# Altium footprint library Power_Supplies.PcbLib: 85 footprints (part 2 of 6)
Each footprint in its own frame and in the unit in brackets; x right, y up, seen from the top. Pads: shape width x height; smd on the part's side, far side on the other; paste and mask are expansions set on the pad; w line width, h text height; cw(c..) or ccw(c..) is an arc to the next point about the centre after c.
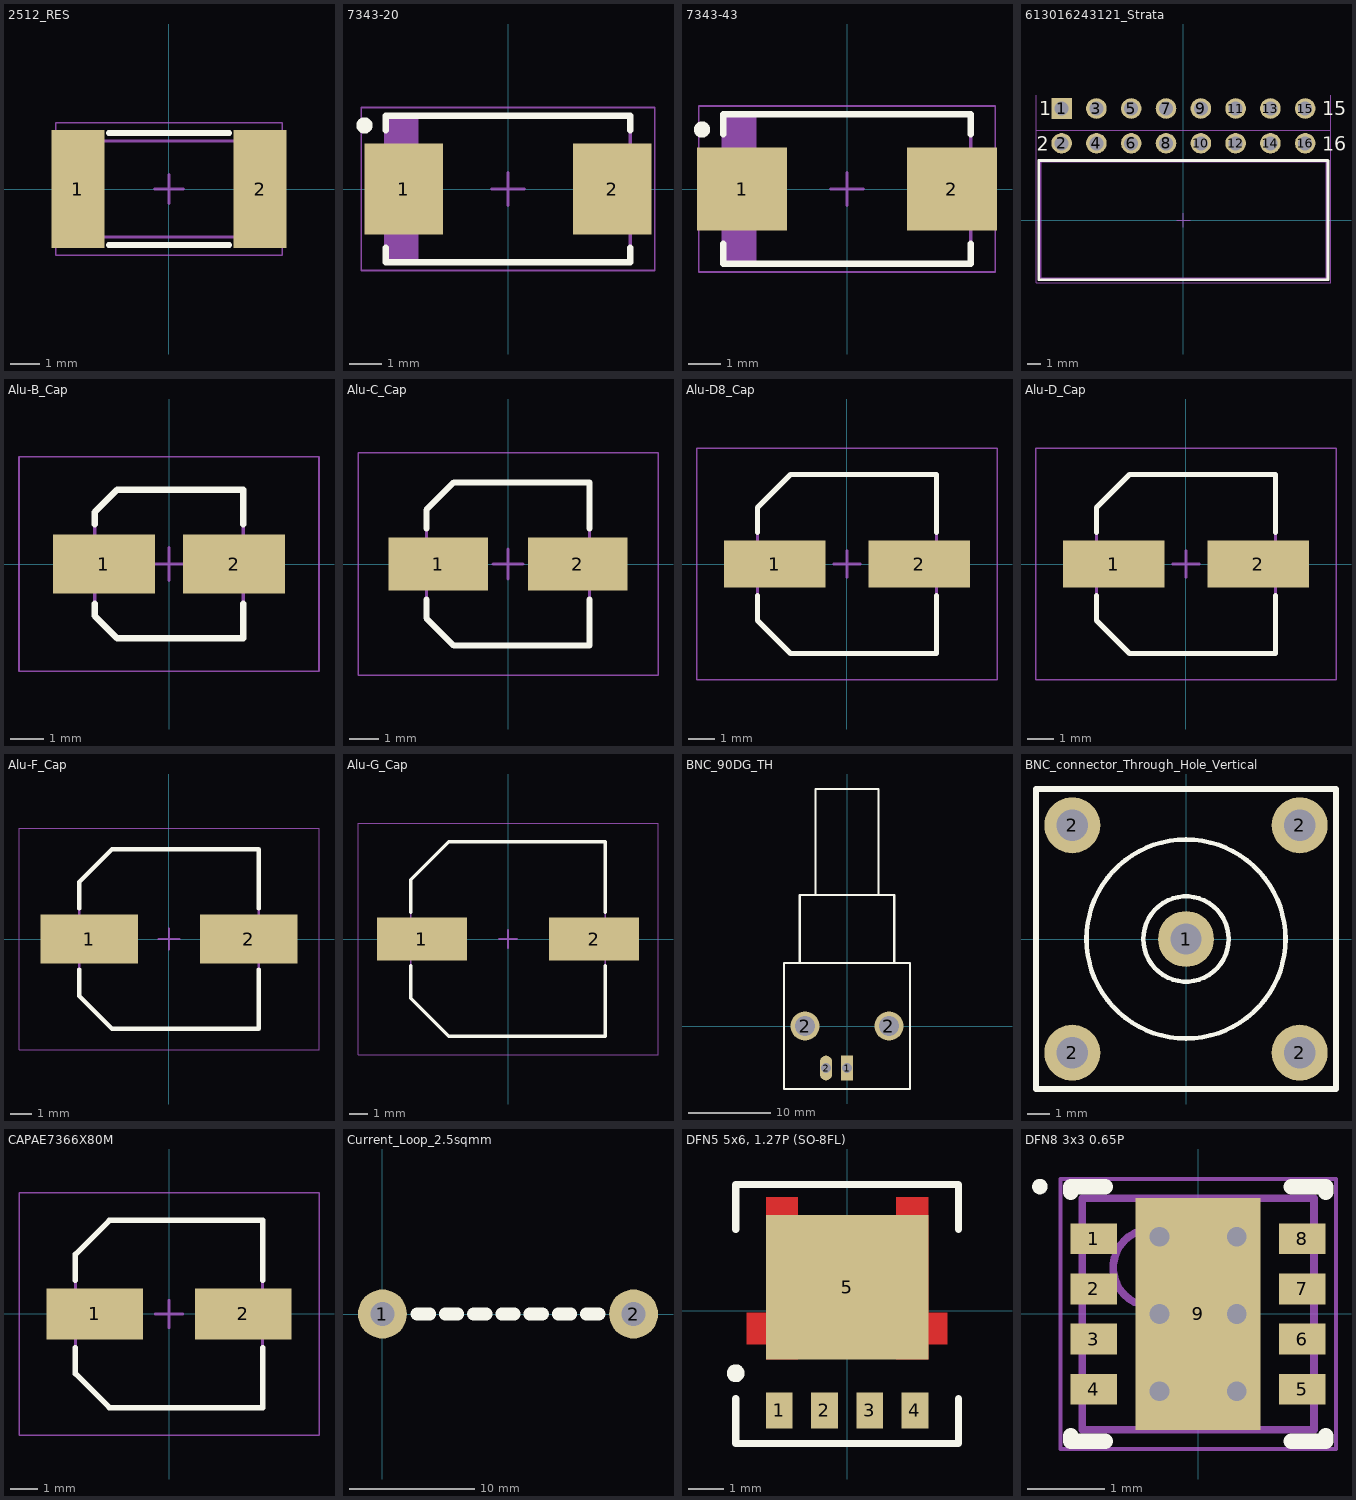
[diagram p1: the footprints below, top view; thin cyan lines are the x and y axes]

## 2512_RES [mm] "2512, Reflow, YAGEO"
height 0.65
pads (2):
  rect 1.8x4 smd: 1(-3.1,0) 2(3.1,0)
Top Overlay:
  lines w0.2: -2.05,-1.9 2.05,-1.9 ; -2.05,1.9 2.05,1.9
Mechanical 13:
  lines w0.1: -3.225,-1.625 -3.225,1.625 3.225,1.625 3.225,-1.625 -3.225,-1.625
Mechanical 15:
  lines w0.05: -3.85,-2.25 -3.85,2.25 3.85,2.25 3.85,-2.25 -3.85,-2.25
  lines w0.1: -0.5,0 0.5,0 ; 0,-0.5 0,0.5
3D body "2512_RES.step": height 0.65, standoff 0, extent -3.225,-1.625 3.225,1.625

## 7343-20 [mm] "7343-20, Polymer Aluminum Electrolytic Capacitors, GX Series, ody 7.3x4.3x1.9 mm"
height 2
pads (2):
  rect 2.4x2.8 smd: 1(-3.2,0) 2(3.2,0)
Top Overlay:
  circle w0.25: c-4.4,1.95 r0.125
  lines w0.2: -3.75,-1.8 -3.75,-2.25 3.75,-2.25 3.75,-1.8 ; -3.75,1.8 -3.75,2.25 3.75,2.25 3.75,1.8
Mechanical 13:
  rectangle: -3.75,-2.25 -2.741,2.25
  lines w0.1: -3.75,-2.25 3.75,-2.25 3.75,2.25 -3.75,2.25 -3.75,-2.25
Mechanical 15:
  lines w0.05: -4.5,-2.5 4.5,-2.5 4.5,2.5 -4.5,2.5 -4.5,-2.5
  lines w0.1: -0.5,0 0.5,0 ; 0,-0.5 0,0.5
3D body "7343-20.step": height 2, standoff 0, extent -3.97,-2.25 3.97,2.25

## 7343-43 [mm] "7343-43, Molded Capacitor, 2-Leads, Body 7.30x4.30mm, IPC Medium Density"
height 4.3
pads (2):
  rect 2.77x2.55 smd: 1(-3.22,0) 2(3.22,0)
Top Overlay:
  circle w0.25: c-4.45,1.825 r0.125
  lines w0.2: -3.8,-1.675 -3.8,-2.3 3.8,-2.3 3.8,-1.675 ; -3.8,1.675 -3.8,2.3 3.8,2.3 3.8,1.675
Mechanical 13:
  rectangle: -3.8,-2.3 -2.778,2.3
  lines w0.1: -3.8,-2.3 -3.8,2.3 3.8,2.3 3.8,-2.3 -3.8,-2.3
Mechanical 15:
  lines w0.05: -4.55,-2.55 -4.55,2.55 4.55,2.55 4.55,-2.55 -4.55,-2.55
  lines w0.1: -0.5,0 0.5,0 ; 0,-0.5 0,0.5
3D body "7343-43.step": height 4.3, standoff 0, extent -4.02,-2.3 4.02,2.3

## 613016243121_Strata [mm] "Socket Header, Pitch 2.54 mm, THT, Angled, dual row, 16p"
height 5.08
pads (16):
  rect 1.5x1.5 hole 1.02: 1(-8.89,8.15)
  round 1.5 hole 1.02: 2(-8.89,5.61) 3(-6.35,8.15) 4(-6.35,5.61) 5(-3.81,8.15) 6(-3.81,5.61) 7(-1.27,8.15) 8(-1.27,5.61) 9(1.27,8.15) 10(1.27,5.61) 11(3.81,8.15) 12(3.81,5.61) 13(6.35,8.15) 14(6.35,5.61) 15(8.89,8.15) 16(8.89,5.61)
Top Overlay:
  lines w0.2: -10.56,-4.35 10.56,-4.35 10.56,4.35 -10.56,4.35 -10.56,-4.35
  text "15" at 10.12,7.64 h1.02
  text "16" at 10.12,5.06 h1.02
  text "1" at -10.52,7.64 h1.02
  text "2" at -10.72,5.06 h1.02
Mechanical 13:
  lines w0.1: -10.41,-4.25 10.41,-4.25 10.41,4.25 -10.41,4.25 -10.41,-4.25
Mechanical 15:
  lines w0.05: -10.76,6.56 10.76,6.56 ; -10.76,9.1 -10.76,-4.55 10.76,-4.55 10.76,9.1 ; -0.5,0 0.5,0 ; 0,-0.5 0,0.5
3D body "613016243121.stp": height 5.05, standoff -3.25, extent -10.41,-4.25 10.41,8.35

## Alu-B_Cap [mm] "Aluminum Electrolytic Capacitor, Body 4.30x4.30x6.10mm, IPC Low Density"
height 6.1
pads (2):
  rect 3.1x1.8 smd: 1(-1.975,0) 2(1.975,0)
Top Overlay:
  lines w0.2: -2.25,-1.2 -2.25,-1.575 -1.575,-2.25 2.25,-2.25 2.25,-1.2 ; -2.25,1.2 -2.25,1.575 -1.575,2.25 2.25,2.25 2.25,1.2
Mechanical 13:
  lines w0.1: -2.25,-1.575 -2.25,1.575 -1.575,2.25 2.25,2.25 2.25,-2.25 -1.575,-2.25 -2.25,-1.575
Mechanical 15:
  lines w0.05: -4.55,-3.25 4.55,-3.25 4.55,3.25 -4.55,3.25 -4.55,-3.25
  lines w0.1: -0.5,0 0.5,0 ; 0,-0.5 0,0.5
3D body "D40H54_Alu-B_CapSMD.STEP": height 5.4, standoff 0, extent -2.3,-2.15 2.3,2.15

## Alu-C_Cap [mm] "Aluminum Electrolytic Capacitor, Body 5.30x5.30x6.10mm, IPC Low Density"
height 6.1
pads (2):
  rect 3.35x1.8 smd: 1(-2.35,0) 2(2.35,0)
Top Overlay:
  lines w0.2: -2.75,-1.2 -2.75,-1.825 -1.825,-2.75 2.75,-2.75 2.75,-1.2 ; -2.75,1.2 -2.75,1.825 -1.825,2.75 2.75,2.75 2.75,1.2
Mechanical 13:
  lines w0.1: -2.75,-1.825 -1.825,-2.75 2.75,-2.75 2.75,2.75 -1.825,2.75 -2.75,1.825 -2.75,-1.825
Mechanical 15:
  lines w0.05: -5.05,-3.75 -5.05,3.75 5.05,3.75 5.05,-3.75 -5.05,-3.75
  lines w0.1: -0.5,0 0.5,0 ; 0,-0.5 0,0.5
3D body "D50H54_Alu-C_CapSMD.STEP": height 5.41, standoff 0, extent -2.95,-2.65 2.95,2.65

## Alu-D8_Cap [mm] "Aluminum Electrolytic Capacitor, Body 6.60x6.60x8.00mm, IPC Low Density"
height 8
pads (2):
  rect 3.85x1.8 smd: 1(-2.75,0) 2(2.75,0)
Top Overlay:
  lines w0.2: -3.4,-1.2 -3.4,-2.15 -2.15,-3.4 3.4,-3.4 3.4,-1.2 ; -3.4,1.2 -3.4,2.15 -2.15,3.4 3.4,3.4 3.4,1.2
Mechanical 13:
  lines w0.1: -3.4,-2.15 -3.4,2.15 -2.15,3.4 3.4,3.4 3.4,-3.4 -2.15,-3.4 -3.4,-2.15
Mechanical 15:
  lines w0.05: -5.7,-4.4 5.7,-4.4 5.7,4.4 -5.7,4.4 -5.7,-4.4
  lines w0.1: -0.5,0 0.5,0 ; 0,-0.5 0,0.5
3D body "D63H77_Alu-D8_CapSMD.STEP": height 7.7, standoff 0, extent -3.5,-3.3 3.5,3.3

## Alu-D_Cap [mm] "Aluminum Electrolytic Capacitor, Body 6.60x6.60x8.00mm, IPC Low Density"
height 8
pads (2):
  rect 3.85x1.8 smd: 1(-2.75,0) 2(2.75,0)
Top Overlay:
  lines w0.2: -3.4,-1.2 -3.4,-2.15 -2.15,-3.4 3.4,-3.4 3.4,-1.2 ; -3.4,1.2 -3.4,2.15 -2.15,3.4 3.4,3.4 3.4,1.2
Mechanical 13:
  lines w0.1: -3.4,-2.15 -2.15,-3.4 3.4,-3.4 3.4,3.4 -2.15,3.4 -3.4,2.15 -3.4,-2.15
Mechanical 15:
  lines w0.05: -5.7,-4.4 -5.7,4.4 5.7,4.4 5.7,-4.4 -5.7,-4.4
  lines w0.1: -0.5,0 0.5,0 ; 0,-0.5 0,0.5
3D body "D63H54_Alu-D_CapSMD.STEP": height 5.4, standoff 0, extent -3.5,-3.3 3.5,3.3

## Alu-F_Cap [mm] "Aluminum Electrolytic Capacitor, Body 8.30x8.30x10.50mm, IPC Low Density"
height 10.5
pads (2):
  rect 4.6x2.3 smd: 1(-3.775,0) 2(3.775,0)
Top Overlay:
  lines w0.2: -4.25,-1.45 -4.25,-2.7 -2.7,-4.25 4.25,-4.25 4.25,-1.45 ; -4.25,1.45 -4.25,2.7 -2.7,4.25 4.25,4.25 4.25,1.45
Mechanical 13:
  lines w0.1: -4.25,-2.7 -4.25,2.7 -2.7,4.25 4.25,4.25 4.25,-4.25 -2.7,-4.25 -4.25,-2.7
Mechanical 15:
  lines w0.05: -7.1,-5.25 7.1,-5.25 7.1,5.25 -7.1,5.25 -7.1,-5.25
  lines w0.1: -0.5,0 0.5,0 ; 0,-0.5 0,0.5
3D body "D80H102_Alu-F_CapSMD.STEP": height 10.2, standoff 0, extent -4.95,-4.15 4.95,4.15

## Alu-G_Cap [mm] "Aluminum Electrolytic Capacitor, Body 10.30x10.30x10.50mm, IPC Low Density"
height 10.5
pads (2):
  rect 4.85x2.3 smd: 1(-4.65,0) 2(4.65,0)
Top Overlay:
  lines w0.2: -5.25,-1.45 -5.25,-3.2 -3.2,-5.25 5.25,-5.25 5.25,-1.45 ; -5.25,1.45 -5.25,3.2 -3.2,5.25 5.25,5.25 5.25,1.45
Mechanical 13:
  lines w0.1: -5.25,-3.2 -3.2,-5.25 5.25,-5.25 5.25,5.25 -3.2,5.25 -5.25,3.2 -5.25,-3.2
Mechanical 15:
  lines w0.05: -8.1,-6.25 -8.1,6.25 8.1,6.25 8.1,-6.25 -8.1,-6.25
  lines w0.1: -0.5,0 0.5,0 ; 0,-0.5 0,0.5
3D body "D100H102_Alu-G_CapSMD.STEP": height 10.2, standoff 0, extent -5.8,-5.15 5.8,5.15

## BNC_90DG_TH [mm]
pads (4):
  rect 1.5x3 hole 1.2: 1(0,-5.08)
  round 3.5 hole 2.4: 2(-5.08,0) 2(5.08,0)
  oval 1.5x3 hole 1.2: 2(-2.54,-5.08)
Top Overlay:
  lines w0.254: -5.715,7.62 -5.715,15.875 5.715,15.875 5.715,7.62 ; -3.81,15.875 -3.81,28.702 3.81,28.702 3.81,15.875 ; -7.62,-7.62 -7.62,7.62 7.62,7.62 7.62,-7.62 -7.62,-7.62
3D body "BNC_90deg1.step": height 15.73, standoff -3.87, extent -7.2,-6.604 7.2,28.296

## BNC_connector_Through_Hole_Vertical [mm]
pads (5):
  round 2.5 hole 1.4: 1(0,0) 2(-5.08,-5.08) 2(-5.08,5.08) 2(5.08,-5.08) 2(5.08,5.08)
Top Overlay:
  circle w0.203: c0,0 r4.445
  circle w0.203: c0,0 r1.905
  lines w0.254: -6.7,-6.7 -6.7,6.7 6.7,6.7 6.7,-6.7 -6.7,-6.7
3D body "BNC.step": height 22.5, standoff -4, extent -6,-6.006 6,5.994

## CAPAE7366X80M [mm] "Aluminum Electrolytic Capacitor, Body 6.60x6.60x8.00mm, IPC Low Density"
height 8
pads (2):
  rect 3.5x1.85 smd: 1(-2.7,0) 2(2.7,0)
Top Overlay:
  lines w0.2: -3.4,-1.225 -3.4,-2.163 -2.163,-3.4 3.4,-3.4 3.4,-1.225 ; -3.4,1.225 -3.4,2.163 -2.163,3.4 3.4,3.4 3.4,1.225
Mechanical 13:
  lines w0.1: -3.4,-2.163 -2.163,-3.4 3.4,-3.4 3.4,3.4 -2.163,3.4 -3.4,2.163 -3.4,-2.163
Mechanical 15:
  lines w0.05: -5.45,-4.4 -5.45,4.4 5.45,4.4 5.45,-4.4 -5.45,-4.4
  lines w0.1: -0.5,0 0.5,0 ; 0,-0.5 0,0.5
3D body "CAPAE7366X80M.step": height 8, standoff 0, extent -3.65,-3.4 3.65,3.4

## Current_Loop_2.5sqmm [mm]
pads (2):
  round 3.9 / inner round 2.9 / far side round 3.9 hole 1.9: 1(0,0) 2(20,0)
Top Overlay:
  lines w1: 2.75,0 3.75,0 ; 5,0 6,0 ; 7.25,0 8.25,0 ; 9.5,0 10.5,0 ; 11.75,0 12.75,0 ; 14,0 15,0 ; 16.25,0 17.25,0

## DFN5 5x6, 1.27P (SO-8FL) [mm]
height 1
pads (5):
  rect 0.75x1 smd: 1(-1.905,-2.795) 2(-0.635,-2.795) 3(0.635,-2.795) 4(1.905,-2.795)
  rect 4.56x4.055 smd: 5(0,0.66)
Top Layer:
  region: 2.825,-0.04 -2.825,-0.04 -2.825,-0.94 2.825,-0.94
  region: 2.28,-1.365 2.28,3.2 1.375,3.2 1.375,-1.365
  region: -1.375,-1.367 -1.375,3.2 -2.281,3.2 -2.281,-1.367
Top Overlay:
  circle w0.25: c-3.125,-1.75 r0.125
  lines w0.2: -3.125,-2.468 -3.125,-3.718 3.125,-3.718 3.125,-2.468 ; -3.125,2.293 -3.125,3.543 3.125,3.543 3.125,2.293
Top Solder:
  region: 2.925,0.06 -2.925,0.06 -2.925,-1.04 2.925,-1.04
  region: -1.275,-1.465 -1.275,3.3 -2.388,3.3 -2.388,-1.465
  region: 2.383,-1.465 2.383,3.3 1.27,3.3 1.27,-1.465
3D body "SO8FL.STEP": height 1.13, standoff 0, extent -2.575,-3.125 2.575,3.025

## DFN8 3x3 0.65P [mm] "DFN8 3x3 0.65P, CASE 506CS, Issue O"
height 1
pads (9):
  rect 0.6x0.4 smd: 1(-1.35,0.975) 2(-1.35,0.325) 3(-1.35,-0.325) 4(-1.35,-0.975) 5(1.35,-0.975) 6(1.35,-0.325) 7(1.35,0.325) 8(1.35,0.975)
  rect 1.62x3 smd: 9(0,0)
via -0.5,1 diameter 0.508 hole 0.254
via 0.5,1 diameter 0.508 hole 0.254
via -0.5,0 diameter 0.508 hole 0.254
via 0.5,0 diameter 0.508 hole 0.254
via -0.5,-1 diameter 0.508 hole 0.254
via 0.5,-1 diameter 0.508 hole 0.254
Top Overlay:
  circle w0.1: c-2.05,1.65 r0.05
  lines w0.2: -1.65,-1.575 -1.65,-1.65 -1.205,-1.65 ; -1.65,1.575 -1.65,1.65 -1.205,1.65 ; 1.205,-1.65 1.65,-1.65 1.65,-1.575 ; 1.205,1.65 1.65,1.65 1.65,1.575
Mechanical 13:
  circle w0.1: c-0.6,0.6 r0.5
  lines w0.1: -1.5,-1.5 -1.5,1.5 1.5,1.5 1.5,-1.5 -1.5,-1.5
Mechanical 15:
  lines w0.05: -1.785,-1.75 -1.785,1.75 1.785,1.75 1.785,-1.75 -1.785,-1.75
  lines w0.1: -0.5,0 0.5,0 ; 0,-0.5 0,0.5
3D body "DFN8 3x3 0.65P.step": height 1, standoff 0, extent -1.501,-1.5 1.501,1.5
